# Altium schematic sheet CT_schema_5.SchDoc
size 297 x 173 mm
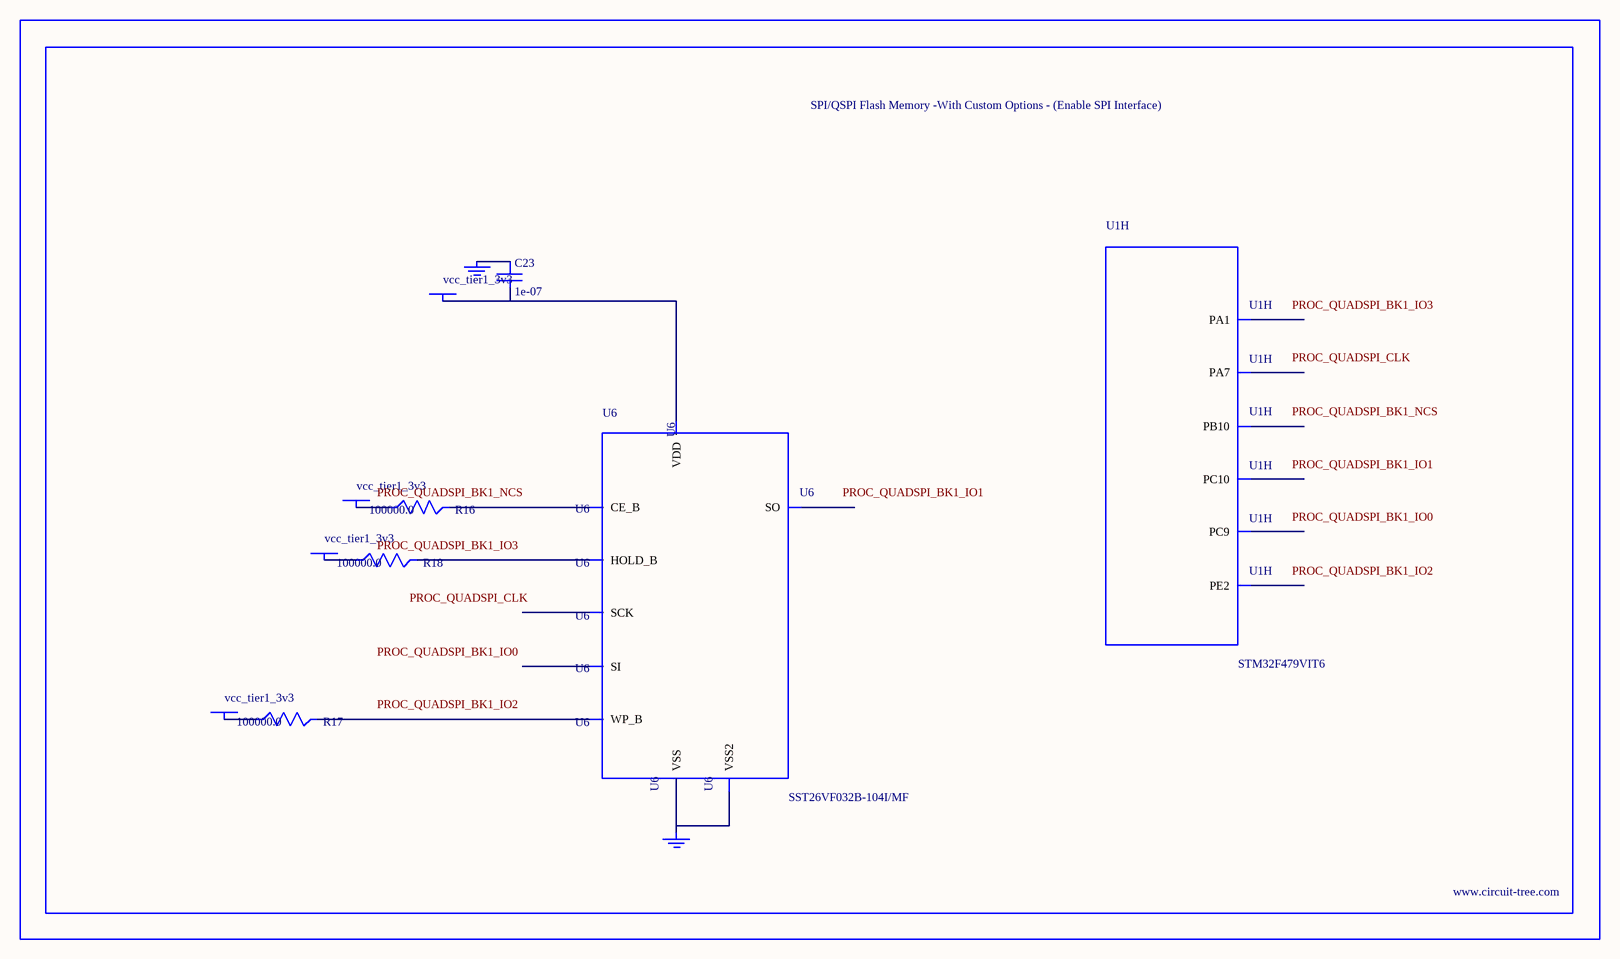
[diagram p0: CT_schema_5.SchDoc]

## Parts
BORDER4  (no value)
C23  1e-07  [C0402]
GND_INSTANCE_4_0  (no value)
GND_INSTANCE_4_1  (no value)
POWER_INSTANCE_4_0  vcc_tier1_3v3
POWER_INSTANCE_4_1  vcc_tier1_3v3
POWER_INSTANCE_4_2  vcc_tier1_3v3
POWER_INSTANCE_4_3  vcc_tier1_3v3
R16  100000.0  [R0603]
R17  100000.0  [R0603]
R18  100000.0  [R0603]
U1  STM32F479VIT6  [LQFP100]  (part H of 9)
U6  SST26VF032B-104I/MF  [WFDN-8]

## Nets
NetC23_1: C23.1 GND_INSTANCE_4_0.0(GND)
NetC23_2: C23.2 POWER_INSTANCE_4_3.0(PWR) U6.8(VDD)
NetGND_INSTANCE_4_1_0: GND_INSTANCE_4_1.0(GND) U6.4(VSS) U6.9(VSS2)
NetPOWER_INSTANCE_4_0_0: POWER_INSTANCE_4_0.0(PWR) R16.1
NetPOWER_INSTANCE_4_1_0: POWER_INSTANCE_4_1.0(PWR) R17.1
NetPOWER_INSTANCE_4_2_0: POWER_INSTANCE_4_2.0(PWR) R18.1
NetR16_2: R16.2 U6.1(CE_B)
NetR17_2: R17.2 U6.3(WP_B)
NetR18_2: R18.2 U6.7(HOLD_B)

Not connected (* = marked no-connect by the designer): U1 1(PE2) 20(PA1) 28(PA7) 41(PB10) 69(PC9) 81(PC10); U6 2(SO) 5(SI) 6(SCK)

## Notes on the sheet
- Labels drawn without touching a wire or pin: PROC_QUADSPI_BK1_IO0, PROC_QUADSPI_BK1_IO1, PROC_QUADSPI_BK1_IO2, PROC_QUADSPI_BK1_IO3, PROC_QUADSPI_BK1_NCS, PROC_QUADSPI_CLK

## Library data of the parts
BORDER4 = BORDER_PAGE4
C23 = C0402C104K3RACTU
GND_INSTANCE_4_0 GND_INSTANCE_4_1 = GND
POWER_INSTANCE_4_0-POWER_INSTANCE_4_3 = PWR
R16-R18 = RC0603JR-07100KL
